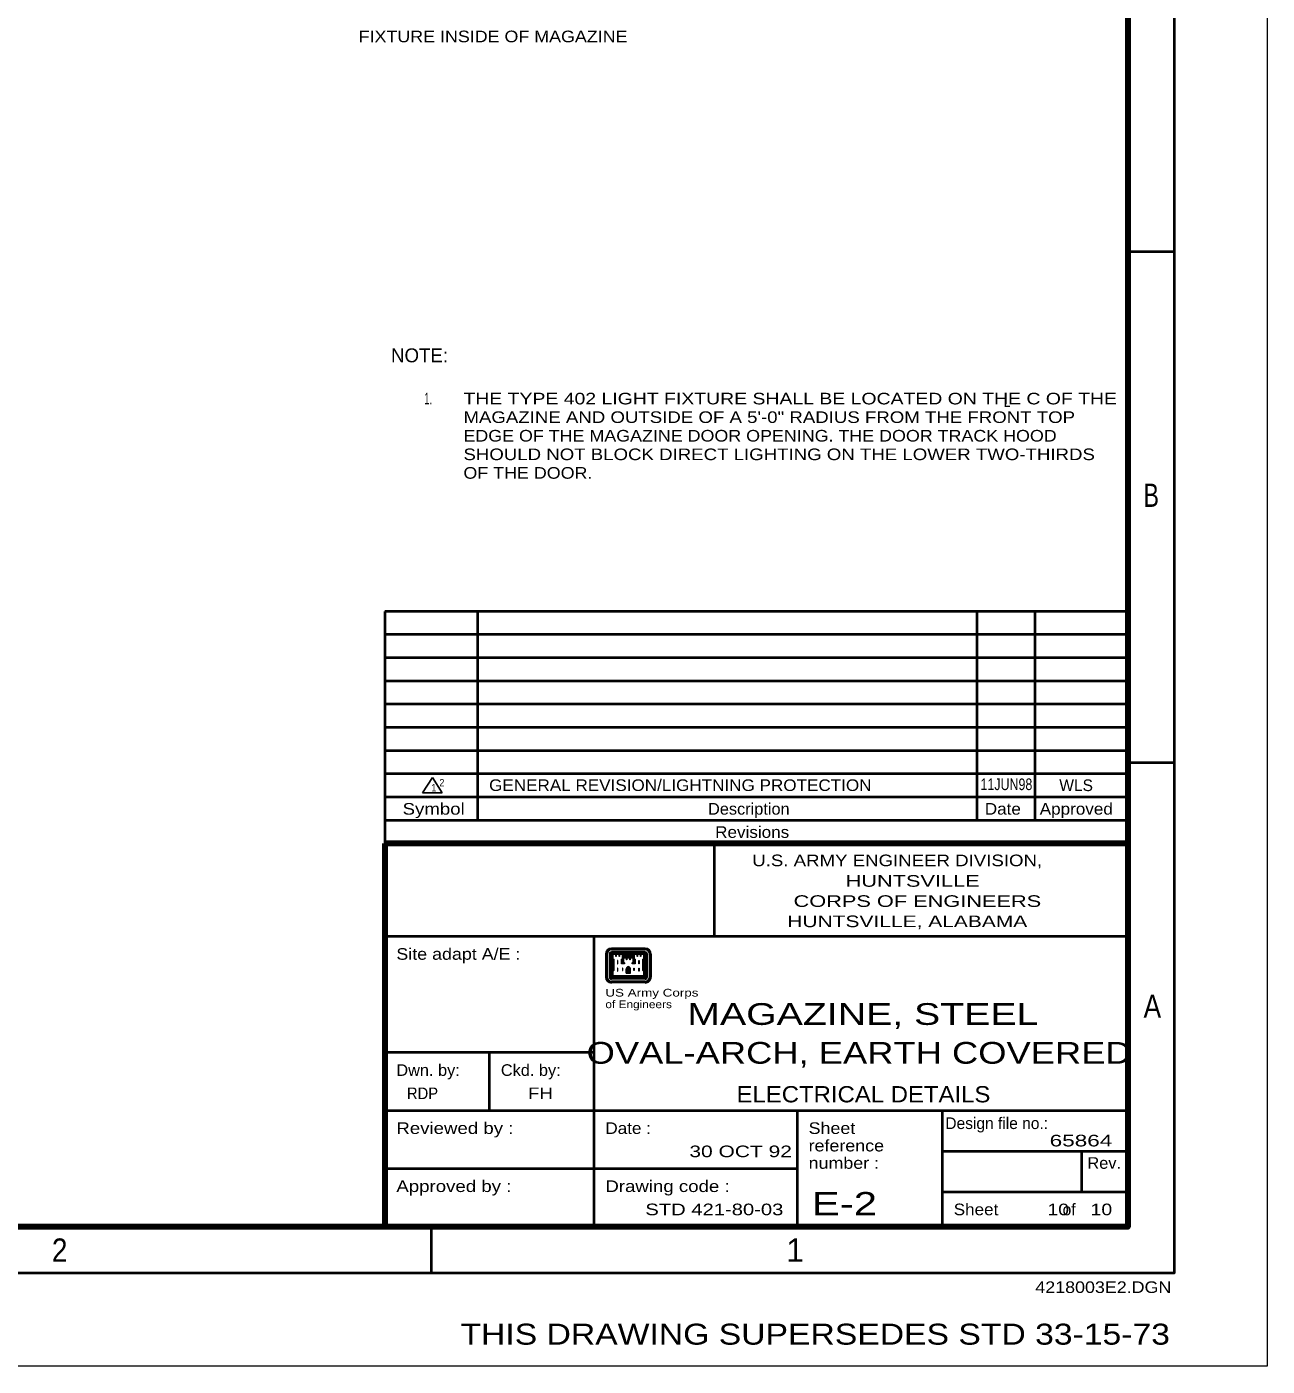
# Model space of a CAD drawing. Extents: x -39.6 to 16.1, y -17.6 to 34.
# Drawn here: x 2.75 to 16.1, y -17.59 to -3.17 of the extents above; entities that cross this region are included whole.
import ezdxf
from ezdxf.enums import TextEntityAlignment as Align

# ---------------------------------------------------------------- set-up
doc = ezdxf.new("R2010")
doc.units = 0
doc.header["$LTSCALE"] = 0.05
doc.layers.add('1', color=7, linetype='Continuous', lineweight=13)
doc.layers.add('2', color=7, linetype='Continuous', lineweight=13)

msp = doc.modelspace()

# ---------------------------------------------------------------- linework, layer by layer
at = {"layer": '1', "lineweight": 40}
for p, q in [((14.60179, -5.59158), (15.10179, -5.59158)), ((6.60179, -9.46658), (6.60179, -11.96658)), ((14.60179, -9.46658), (6.60179, -9.46658)), ((7.60179, -9.46658), (7.60179, -11.71658)), ((12.97679, -9.46658), (12.97679, -11.71658)), ((13.60179, -9.46658), (13.60179, -11.71658)), ((14.60179, -9.71658), (6.60179, -9.71658)), ((14.60179, -9.96658), (6.60179, -9.96658)), ((14.60179, -10.21658), (6.60179, -10.21658)), ((14.60179, -10.46658), (6.60179, -10.46658)), ((14.60179, -10.71658), (6.60179, -10.71658)), ((14.60179, -10.96658), (6.60179, -10.96658)), ((14.60179, -11.09158), (15.10179, -11.09158)), ((14.60179, -11.21658), (6.60179, -11.21658)), ((14.60179, -11.46658), (6.60179, -11.46658)), ((14.60179, -11.71658), (6.60179, -11.71658)), ((10.14979, -11.96658), (10.14979, -12.96658)), ((14.60179, -12.96658), (6.60179, -12.96658)), ((8.85179, -12.96658), (8.85179, -16.09158)), ((8.85179, -14.21658), (6.60179, -14.21658)), ((7.72679, -14.21658), (7.72679, -14.84158)), ((14.60179, -14.84158), (6.60179, -14.84158)), ((11.03979, -14.84158), (11.03979, -16.09158)), ((12.60179, -14.84158), (12.60179, -16.09158)), ((14.60179, -15.27958), (12.60179, -15.27958)), ((14.10179, -15.27958), (14.10179, -15.71658)), ((11.03979, -15.46658), (6.60179, -15.46658)), ((14.60179, -15.71658), (12.60179, -15.71658)), ((7.10179, -16.09158), (7.10179, -16.59158))]:
    msp.add_line(p, q, dxfattribs=at)
at = {"layer": '1', "lineweight": 25}
for p, q in [((7.00873, -11.42035), (7.11512, -11.25316)), ((7.22153, -11.42035), (7.11512, -11.25316)), ((7.00873, -11.42035), (7.22153, -11.42035))]:
    msp.add_line(p, q, dxfattribs=at)
at = {"layer": '1', "lineweight": 90}
for p, q in [((6.60179, -11.96658), (6.60179, -16.09158)), ((14.60179, -11.96658), (6.60179, -11.96658))]:
    msp.add_line(p, q, dxfattribs=at)
at = {"layer": '1'}
for p, q in [((9.40579, -13.09158), (9.04179, -13.09158)), ((9.40579, -13.09558), (9.04179, -13.09558)), ((9.40579, -13.10058), (9.04179, -13.10058)), ((9.40579, -13.10558), (9.04179, -13.10558)), ((9.40579, -13.11158), (9.04179, -13.11158)), ((8.97679, -13.15658), (8.97679, -13.40258)), ((8.98079, -13.15658), (8.98079, -13.40258)), ((8.98679, -13.15658), (8.98679, -13.40258)), ((8.99179, -13.15658), (8.99179, -13.40258)), ((8.99679, -13.15658), (8.99679, -13.40258)), ((9.01779, -13.15658), (9.01779, -13.40258)), ((9.02279, -13.15658), (9.02279, -13.40258)), ((9.02779, -13.15658), (9.02779, -13.40258)), ((9.03279, -13.15658), (9.03279, -13.40258)), ((9.03779, -13.15658), (9.03779, -13.40258)), ((9.40579, -13.13158), (9.04179, -13.13158)), ((9.40579, -13.13758), (9.04179, -13.13758)), ((9.40579, -13.14258), (9.04179, -13.14258)), ((9.40579, -13.14758), (9.04179, -13.14758)), ((9.40579, -13.15258), (9.04179, -13.15258)), ((9.04379, -13.15658), (9.04379, -13.40058)), ((9.04879, -13.15658), (9.04879, -13.39558)), ((9.05279, -13.20858), (9.05279, -13.33458)), ((9.05779, -13.21358), (9.05779, -13.32858)), ((9.16779, -13.15758), (9.27979, -13.15758)), ((9.16779, -13.16258), (9.27979, -13.16258)), ((9.16779, -13.16758), (9.27979, -13.16758)), ((9.16779, -13.17358), (9.27979, -13.17358)), ((9.16779, -13.17858), (9.27979, -13.17858)), ((9.16779, -13.18358), (9.27979, -13.18358)), ((9.16779, -13.18858), (9.27979, -13.18858)), ((9.38979, -13.21358), (9.38979, -13.32858)), ((9.39479, -13.20858), (9.39479, -13.33358)), ((9.39879, -13.15658), (9.39879, -13.39558)), ((9.40379, -13.15658), (9.40379, -13.40058)), ((9.40879, -13.15658), (9.40879, -13.40258)), ((9.41479, -13.15658), (9.41479, -13.40258)), ((9.41979, -13.15658), (9.41979, -13.40258)), ((9.42479, -13.15658), (9.42479, -13.40258)), ((9.42979, -13.15658), (9.42979, -13.40258)), ((9.45079, -13.15658), (9.45079, -13.40258)), ((9.45579, -13.15658), (9.45579, -13.40258)), ((9.46179, -13.15658), (9.46179, -13.40258)), ((9.46679, -13.15658), (9.46679, -13.40258)), ((9.46979, -13.15658), (9.46979, -13.40258)), ((9.40579, -13.40558), (9.04179, -13.40558)), ((9.40379, -13.40058), (9.04379, -13.40058)), ((9.39879, -13.39558), (9.04879, -13.39558)), ((9.19979, -13.35958), (9.19979, -13.31958)), ((9.19979, -13.35958), (9.24779, -13.35958)), ((9.20479, -13.35958), (9.20479, -13.31958)), ((9.20979, -13.35958), (9.20979, -13.31958)), ((9.21479, -13.35958), (9.21479, -13.31958)), ((9.22079, -13.35958), (9.22079, -13.31958)), ((9.22679, -13.35958), (9.22679, -13.31958)), ((9.23179, -13.35958), (9.23179, -13.31958)), ((9.23779, -13.35958), (9.23779, -13.31958)), ((9.24279, -13.35958), (9.24279, -13.31958)), ((9.24779, -13.35958), (9.24779, -13.31958)), ((9.40579, -13.41058), (9.04179, -13.41058)), ((9.40579, -13.41658), (9.04179, -13.41658)), ((9.40579, -13.42158), (9.04179, -13.42158)), ((9.40579, -13.42658), (9.04179, -13.42658)), ((9.40579, -13.44758), (9.04179, -13.44758)), ((9.40579, -13.45258), (9.04179, -13.45258)), ((9.40579, -13.45758), (9.04179, -13.45758)), ((9.40579, -13.46358), (9.04179, -13.46358)), ((9.40579, -13.46658), (9.04179, -13.46658)), ((16.10179, -17.59158), (-25.89821, -17.59158))]:
    msp.add_line(p, q, dxfattribs=at)
for points in [[(-25.89821, 12.40842), (16.10179, 12.40842), (16.10179, -17.59158)], [(9.16179, -13.21358), (9.15879, -13.21658), (9.15879, -13.25058), (9.16979, -13.25058), (9.16279, -13.24258), (9.16279, -13.21258)], [(9.28579, -13.21358), (9.28879, -13.21658), (9.28879, -13.25058), (9.27779, -13.25058), (9.28479, -13.24258), (9.28479, -13.21258)]]:
    msp.add_lwpolyline(points, dxfattribs=at)
at = {"layer": '1', "lineweight": 40}
msp.add_lwpolyline([(-24.89821, -16.59158), (-24.89821, 11.40842), (15.10179, 11.40842), (15.10179, -16.59158)], close=True, dxfattribs=at)
at = {"layer": '1', "lineweight": 90}
msp.add_lwpolyline([(-23.39821, 10.90842), (14.60179, 10.90842), (14.60179, -16.09158), (-23.39821, -16.09158)], close=True, dxfattribs=at)
at = {"layer": '1'}
for points in [[(9.05279, -13.15658), (9.05279, -13.20358), (9.06279, -13.21358), (9.06279, -13.32858), (9.05279, -13.33958), (9.05279, -13.39158), (9.39479, -13.39158), (9.39479, -13.33958), (9.38379, -13.32858), (9.38379, -13.21358), (9.39479, -13.20358), (9.39479, -13.15658), (9.34979, -13.15658), (9.31479, -13.15658), (9.28279, -13.15658), (9.28279, -13.20358), (9.29379, -13.21358), (9.29379, -13.25558), (9.26879, -13.25558), (9.26879, -13.25158), (9.27979, -13.24058), (9.27979, -13.19358), (9.23479, -13.19358), (9.19979, -13.19358), (9.16779, -13.19358), (9.16779, -13.24058), (9.17879, -13.25158), (9.17879, -13.25558), (9.15379, -13.25558), (9.15379, -13.21358), (9.16479, -13.20358), (9.16479, -13.15658), (9.11879, -13.15658), (9.08479, -13.15658)], [(9.05779, -13.16158), (9.05779, -13.20158), (9.06879, -13.21158), (9.06879, -13.33058), (9.05779, -13.34158), (9.05779, -13.38658), (9.38979, -13.38658), (9.38979, -13.34158), (9.37879, -13.33058), (9.37879, -13.21158), (9.38979, -13.20158), (9.38979, -13.16158), (9.35779, -13.16158), (9.35779, -13.18058), (9.35479, -13.18058), (9.35479, -13.16158), (9.32279, -13.16158), (9.32279, -13.18058), (9.31979, -13.18058), (9.31979, -13.16158), (9.28779, -13.16158), (9.28779, -13.20158), (9.29879, -13.21158), (9.29879, -13.26058), (9.26379, -13.26058), (9.26379, -13.24958), (9.27479, -13.23858), (9.27479, -13.19858), (9.24279, -13.19858), (9.24279, -13.21758), (9.23979, -13.21758), (9.23979, -13.19858), (9.20779, -13.19858), (9.20779, -13.21758), (9.20479, -13.21758), (9.20479, -13.19858), (9.17279, -13.19858), (9.17279, -13.23858), (9.18379, -13.24958), (9.18379, -13.26058), (9.14879, -13.26058), (9.14879, -13.21158), (9.15979, -13.20158), (9.15979, -13.16158), (9.12779, -13.16158), (9.12779, -13.18058), (9.12479, -13.18058), (9.12479, -13.16158), (9.09279, -13.16158), (9.09279, -13.18058), (9.08979, -13.18058), (9.08979, -13.16158)], [(9.10679, -13.22558), (9.10679, -13.26058), (9.10979, -13.26058), (9.10979, -13.22558)], [(9.34079, -13.22558), (9.34079, -13.26058), (9.33679, -13.26058), (9.33679, -13.22558)], [(9.10679, -13.30558), (9.10679, -13.34058), (9.10979, -13.34058), (9.10979, -13.30558)], [(9.16179, -13.30558), (9.16179, -13.33058), (9.16479, -13.33058), (9.16479, -13.30558)], [(9.28579, -13.30558), (9.28579, -13.33058), (9.28279, -13.33058), (9.28279, -13.30558)], [(9.34079, -13.30558), (9.34079, -13.34058), (9.33679, -13.34058), (9.33679, -13.30558)]]:
    msp.add_lwpolyline(points, close=True, dxfattribs=at)
for centre, radius, start, end in [((9.04156, -13.15612), 0.06429, 89.99998, 179.99997), ((9.04156, -13.15612), 0.06057, 89.99998, 179.99997), ((9.04156, -13.15612), 0.05536, 89.99998, 179.99997), ((9.04156, -13.15612), 0.05015, 89.99998, 179.99997), ((9.04156, -13.15612), 0.04494, 89.99998, 179.99997), ((9.40585, -13.15612), 0.06429, 359.99998, 89.99998), ((9.40585, -13.15612), 0.06057, 0.00002, 90.00002), ((9.40585, -13.15612), 0.05536, 0.00003, 90.00002), ((9.40585, -13.15612), 0.05015, 0.00002, 90.00002), ((9.40585, -13.15612), 0.04494, 0.00002, 90.00002), ((9.04156, -13.15612), 0.02411, 89.99998, 179.99997), ((9.04156, -13.15612), 0.0189, 89.99998, 179.99997), ((9.04156, -13.15612), 0.01369, 89.99998, 179.99997), ((9.04156, -13.15612), 0.00848, 89.99998, 179.99997), ((9.04156, -13.15612), 0.00327, 89.99998, 179.99997), ((9.40585, -13.15612), 0.02411, 359.99998, 89.99998), ((9.40585, -13.15612), 0.0189, 359.99998, 89.99998), ((9.40585, -13.15612), 0.01369, 359.99998, 89.99998), ((9.40585, -13.15612), 0.00848, 359.99998, 89.99998), ((9.40585, -13.15612), 0.00327, 359.99998, 89.99998), ((9.04156, -13.40255), 0.06429, 180.00003, 270.00003), ((9.04156, -13.40255), 0.06057, 179.99998, 269.99997), ((9.04156, -13.40255), 0.05536, 179.99998, 269.99997), ((9.04156, -13.40255), 0.05015, 179.99998, 269.99997), ((9.04156, -13.40255), 0.04494, 179.99998, 269.99997), ((9.04156, -13.40255), 0.02411, 180.00003, 270.00003), ((9.04156, -13.40255), 0.0189, 180.00003, 270.00003), ((9.04156, -13.40255), 0.01369, 180.00003, 270.00003), ((9.04156, -13.40255), 0.00848, 180.00003, 270.00003), ((9.04156, -13.40255), 0.00327, 180.00003, 270.00003), ((9.23268, -13.32216), 0.03332, 105.66805, 176.05748), ((9.23268, -13.32216), 0.02811, 103.46979, 176.05748), ((9.23268, -13.32216), 0.0229, 103.46979, 176.05748), ((9.23268, -13.32216), 0.0177, 103.46979, 176.05748), ((9.21473, -13.32216), 0.01249, 3.94252, 76.53021), ((9.21473, -13.32216), 0.0177, 3.94252, 76.53021), ((9.21473, -13.32216), 0.0229, 3.94252, 76.53021), ((9.23268, -13.32216), 0.01249, 103.46979, 176.05748), ((9.21473, -13.32216), 0.02811, 3.94252, 76.53021), ((9.21473, -13.32216), 0.03332, 3.94252, 74.39486), ((9.40585, -13.40255), 0.06429, 270.00003, 0.00003), ((9.40585, -13.40255), 0.02411, 270.00003, 0.00003), ((9.40585, -13.40255), 0.0189, 270.00003, 0.00003), ((9.40585, -13.40255), 0.01369, 270.00003, 0.00003), ((9.40585, -13.40255), 0.00848, 270.00003, 0.00003), ((9.40585, -13.40255), 0.00327, 270.00003, 0.00003), ((9.40585, -13.40255), 0.04494, 270.00002, 0.00002), ((9.40585, -13.40255), 0.05015, 270.00002, 0.00002), ((9.40585, -13.40255), 0.05536, 270.00002, 0.00002), ((9.40585, -13.40255), 0.06057, 270.00002, 0.00002)]:
    msp.add_arc(centre, radius, start, end, dxfattribs=at)

# ---------------------------------------------------------------- texts
for s, height, width, p in [('FIXTURE INSIDE OF MAGAZINE', 0.125, 1.15, (6.32079, -3.34058)), ('1.', 0.125, 0.6, (7.02779, -7.23858)), ('THE TYPE 402 LIGHT FIXTURE SHALL BE LOCATED ON THE C OF THE', 0.125, 1.25, (7.44879, -7.23858)), ('L', 0.125, 0.75, (13.26679, -7.26758)), ('MAGAZINE AND OUTSIDE OF A 5\'-0" RADIUS FROM THE FRONT TOP', 0.125, 1.2, (7.44879, -7.43858)), ('EDGE OF THE MAGAZINE DOOR OPENING. THE DOOR TRACK HOOD', 0.125, 1.15, (7.44879, -7.63858)), ('SHOULD NOT BLOCK DIRECT LIGHTING ON THE LOWER TWO-THIRDS', 0.125, 1.2, (7.44879, -7.83858)), ('OF THE DOOR.', 0.125, 1.15, (7.44879, -8.03858)), ('GENERAL REVISION/LIGHTNING PROTECTION', 0.125, 1.1, (7.72502, -11.39989)), ('11JUN98', 0.125, 0.8, (13.01549, -11.39022)), ('Site adapt A/E :', 0.125, 1.15, (6.72679, -13.21658)), ('US Army Corps', 0.083, 1.3, (8.97679, -13.61258)), ('of Engineers', 0.083, 1.15, (8.97679, -13.73758)), ('Dwn. by:', 0.125, 1.05, (6.72679, -14.46658)), ('Ckd. by:', 0.125, 1.05, (7.85179, -14.46658)), ('Reviewed by :', 0.125, 1.2, (6.72679, -15.09158)), ('Date :', 0.125, 1.1, (8.97679, -15.09158)), ('Sheet', 0.125, 1.15, (11.16479, -15.09158)), ('reference', 0.125, 1.15, (11.16479, -15.27958)), ('number :', 0.125, 1.15, (11.16479, -15.46658)), ('Rev.', 0.125, 1.05, (14.16679, -15.46658)), ('Approved by :', 0.125, 1.2, (6.72679, -15.71658)), ('Drawing code :', 0.125, 1.2, (8.97679, -15.71658)), ('Sheet     ', 0.125, 1.1, (12.72679, -15.96658)), ('4218003E2.DGN', 0.125, 1.15, (13.60557, -16.80335))]:
    msp.add_text(s, height=height, dxfattribs=dict(at, width=width)).set_placement(p)
for s, height, p in [('NOTE:', 0.15, (6.66979, -6.78558)), ('WLS', 0.125, (13.86356, -11.4007)), ('Design file no.:', 0.125, (12.63679, -15.03858))]:
    msp.add_text(s, height=height, dxfattribs=at).set_placement(p)
for s, height, width, p in [('B', 0.25, 0.75, (14.85279, -8.34158)), ('2', 0.08, 0.9, (7.21696, -11.35016)), ('Symbol', 0.125, 1.2, (7.12829, -11.65458)), ('Description', 0.125, 1.05, (10.52129, -11.65458)), ('Date', 0.125, 1.1, (13.25579, -11.65458)), ('Approved', 0.125, 1.1, (14.04629, -11.65458)), ('Revisions', 0.125, 1.1, (10.55729, -11.90458)), ('   U.S. ARMY ENGINEER DIVISION,   ', 0.125, 1.2, (12.11829, -12.20958)), ('           HUNTSVILLE             ', 0.125, 1.4, (12.34979, -12.43058)), ('       CORPS OF ENGINEERS         ', 0.125, 1.4, (12.40079, -12.64758)), ('      HUNTSVILLE, ALABAMA         ', 0.125, 1.35, (12.32079, -12.86558)), ('A', 0.25, 0.85, (14.86529, -13.84158)), ('ELECTRICAL DETAILS', 0.175, 1.1, (11.75529, -14.75158)), ('2', 0.25, 0.9, (3.10229, -16.46658)), ('THIS DRAWING SUPERSEDES STD 33-15-73', 0.226, 1.2, (11.23579, -17.35958))]:
    msp.add_text(s, height=height, dxfattribs=dict(at, width=width)).set_placement(p, align=Align.CENTER)
for height, p in [(0.08, (7.13058, -11.40516)), (0.2503, (11.01879, -16.46658))]:
    msp.add_text('1', height=height, dxfattribs=at).set_placement(p, align=Align.CENTER)
msp.add_text('of', height=0.125, dxfattribs=at).set_placement((14.03879, -15.96658), align=Align.RIGHT)
at = {"layer": '2'}
for s, height, width, p in [('       MAGAZINE, STEEL       ', 0.234, 1.35, (11.74837, -13.91758)), ('  OVAL-ARCH, EARTH COVERED   ', 0.234, 1.25, (11.76292, -14.33558)), ('RDP', 0.125, 0.95, (7.00829, -14.71658)), ('FH ', 0.125, 1.2, (8.30629, -14.71658))]:
    msp.add_text(s, height=height, dxfattribs=dict(at, width=width)).set_placement(p, align=Align.CENTER)
for s, width, p in [('         65864', 1.45, (14.43379, -15.22558)), ('30 OCT 92', 1.35, (10.98479, -15.34158)), ('STD 421-80-03', 1.3, (10.89279, -15.96658)), (' 10    10', 1.25, (14.43279, -15.96658))]:
    msp.add_text(s, height=0.125, dxfattribs=dict(at, width=width)).set_placement(p, align=Align.RIGHT)
at = {"layer": '2', "width": 1.35}
msp.add_text(' E-2  ', height=0.25, dxfattribs=at).set_placement((11.07379, -15.96658))

doc.saveas('drawing.dxf')
